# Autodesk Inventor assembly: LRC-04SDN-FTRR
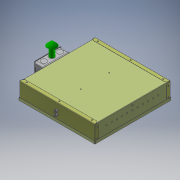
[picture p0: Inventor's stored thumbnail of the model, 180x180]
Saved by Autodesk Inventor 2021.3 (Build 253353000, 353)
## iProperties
Part Number: LRC-04SDN-FTRR
Document SubType Name: Assembly
Designer: JChurch
load_classification: Lighting
motor: 0 ul
Author: JChurch
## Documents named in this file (5)
- X:\Revit Files\0000-Un-Zipped\COB\LRC-04SDN-FTR\LRC-04SDN-FTRR.iam
- X:\INVENTOR\885\885000-00-00.iam
- X:\INVENTOR\830\830520-00-00.ipt
- X:\INVENTOR\750\750480-FT-XX.iam
- X:\Revit Files\0000-Un-Zipped\COB\LRC-04SDN-FTR\LRC-04SDN-FTRR_Substitute_1.ipt
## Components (4 placed, 4 different names)
1. 885000-00-00:1 [sub-assembly] — Mate:4, Mate:5, Angle:1
2. 830520-00-00:1 — Mate:1, Mate:2, Mate:3, Mate:4, Mate:5, Angle:1, Insert:1
3. 750480-FT-XX:1 [sub-assembly] — Insert:1
4. LRC-04SDN-FTRR_Substitute_1:1
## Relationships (7: Mate 5, Angle 1, Insert 1)
- Mate:1: 830520-00-00:1
- Mate:2: 830520-00-00:1
- Mate:3: 830520-00-00:1
- Mate:4: 885000-00-00:1 ↔ 830520-00-00:1
- Mate:5: 885000-00-00:1 ↔ 830520-00-00:1
- Angle:1: 885000-00-00:1 ↔ 830520-00-00:1
- Insert:1: 830520-00-00:1 ↔ 750480-FT-XX:1
